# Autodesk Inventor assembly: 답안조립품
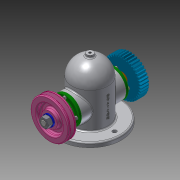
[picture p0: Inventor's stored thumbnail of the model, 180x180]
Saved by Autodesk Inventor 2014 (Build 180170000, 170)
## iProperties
Created: 2019-11
Part Number: 답안조립품
Document SubType Name: Assembly
Designer: OA55
Author: OA55
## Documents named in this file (14)
- C:\Users\OA55\Desktop\491104V1048\답안조립품.iam
- C:\Users\OA55\Desktop\491104V1048\본체.ipt
- C:\Users\OA55\Desktop\491104V1048\커버.ipt
- C:\Users\OA55\Desktop\491104V1048\오일 실 26 38 8.ipt
- C:\Users\OA55\Desktop\491104V1048\베어링 6203.ipt
- C:\Users\OA55\Desktop\491104V1048\축.ipt
- C:\Users\OA55\Desktop\491104V1048\부시.ipt
- C:\Users\OA55\Desktop\491104V1048\키 5x5x12.ipt
- C:\Users\OA55\Desktop\491104V1048\V-벨트풀리.ipt
- V-벨트풀리.ipt
- C:\Users\OA55\Desktop\491104V1048\와셔 12x24.ipt
- C:\Users\OA55\Desktop\491104V1048\너트 M12x1.25.ipt
- C:\Users\OA55\Desktop\491104V1048\스퍼기어.ipt
- C:\Users\OA55\Desktop\491104V1048\볼트 M4.ipt
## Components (1 placed, 1 different names)
1. V-벨트풀리:1 — 각도:4
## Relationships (1: Angle 1)
- 각도:4 [Angle]: V-벨트풀리:1
